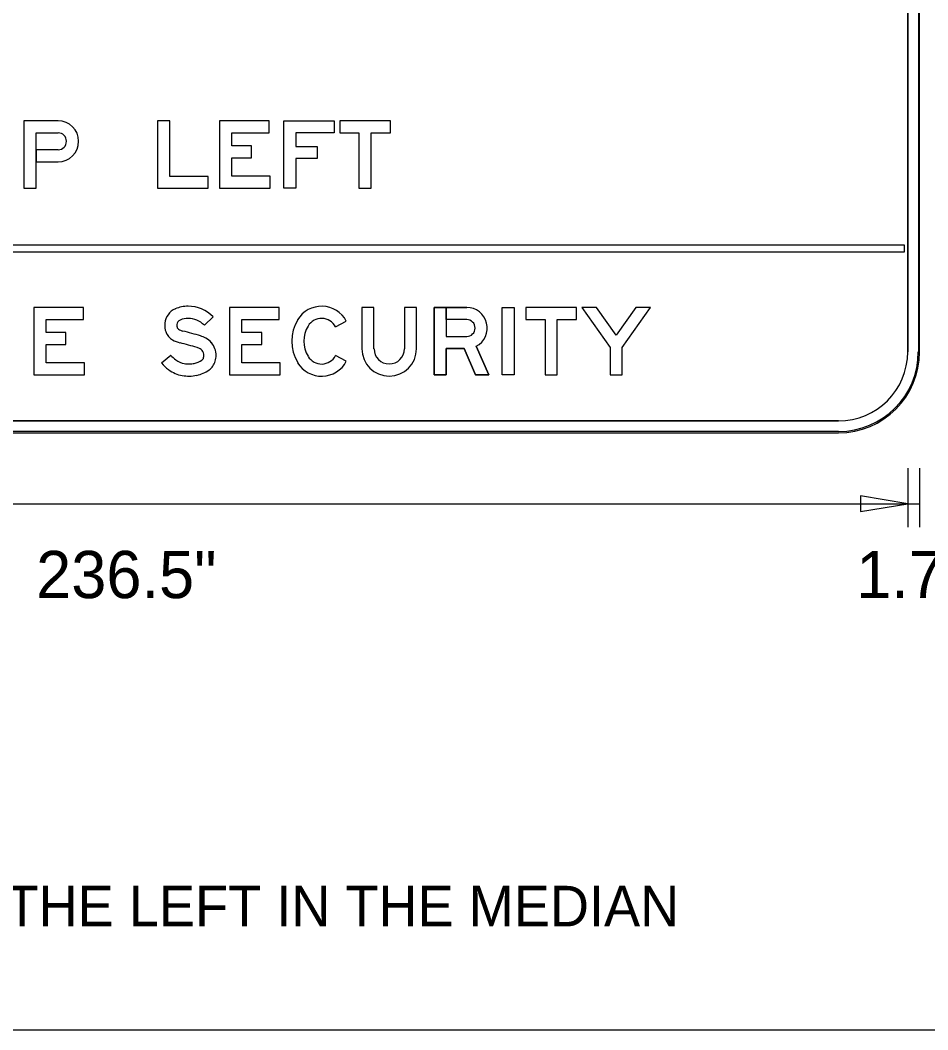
# Model space of a CAD drawing. Extents: x 17890628 to 17890817, y 17897493 to 17897992.
# Drawn here: x 17890707.77 to 17890718.98, y 17897523.4 to 17897535.86 of the extents above; entities that cross this region are included whole.
import ezdxf

# ---------------------------------------------------------------- set-up
doc = ezdxf.new("R2010")
doc.units = 0
for name, color, linetype in [('GSBWFill', 7, 'Continuous'), ('GSColorFill', 7, 'Continuous'), ('GSDims', 7, 'Continuous'), ('GSOutline', 7, 'Continuous'), ('SheetLinesMisc2_dp', 7, 'Continuous')]:
    doc.layers.add(name, color=color, linetype=linetype)

msp = doc.modelspace()

# ---------------------------------------------------------------- linework, layer by layer
at = {"layer": 'GSBWFill'}
for p, q in [((17890718.734, 17897539.769), (17890718.734, 17897531.769)), ((17890718.879, 17897531.769), (17890718.879, 17897539.769)), ((17890707.968, 17897534.471), (17890708.239, 17897534.471)), ((17890718.694, 17897533.087), (17890699.027, 17897533.087)), ((17890718.694, 17897533.004), (17890718.694, 17897533.087)), ((17890699.027, 17897533.004), (17890718.694, 17897533.004)), ((17890712.516, 17897532.316), (17890712.516, 17897531.806)), ((17890711.667, 17897532.077), (17890711.799, 17897532.148)), ((17890711.799, 17897531.652), (17890711.667, 17897531.722)), ((17890711.667, 17897531.722), (17890711.667, 17897531.722)), ((17890717.879, 17897530.915), (17890699.881, 17897530.915)), ((17890699.881, 17897530.769), (17890717.879, 17897530.769))]:
    msp.add_line(p, q, dxfattribs=at)
for points in [[(17890708.239, 17897534.621), (17890707.818, 17897534.621), (17890707.818, 17897533.788), (17890707.968, 17897533.788), (17890707.968, 17897534.471)], [(17890708.239, 17897534.263), (17890707.968, 17897534.263), (17890707.968, 17897534.113), (17890708.239, 17897534.113)], [(17890712.141, 17897531.806), (17890712.141, 17897532.316), (17890711.991, 17897532.316), (17890711.991, 17897531.806)], [(17890712.666, 17897531.806), (17890712.666, 17897532.316), (17890712.516, 17897532.316)], [(17890713.404, 17897531.838), (17890713.558, 17897531.483), (17890713.394, 17897531.483), (17890713.254, 17897531.808), (17890713.033, 17897531.808), (17890713.033, 17897531.483), (17890712.883, 17897531.483), (17890712.883, 17897532.316), (17890713.033, 17897532.316), (17890713.033, 17897531.958), (17890713.286, 17897531.958)], [(17890713.033, 17897532.166), (17890713.033, 17897532.316), (17890713.286, 17897532.316)], [(17890710.153, 17897532.202), (17890710.046, 17897532.097)], [(17890713.286, 17897532.166), (17890713.033, 17897532.166)], [(17890709.516, 17897531.631), (17890709.63, 17897531.729)]]:
    msp.add_lwpolyline(points, dxfattribs=at)
for points in [[(17890710.093, 17897533.788), (17890710.093, 17897533.933), (17890709.618, 17897533.933), (17890709.618, 17897534.621), (17890709.468, 17897534.621), (17890709.468, 17897533.788)], [(17890710.859, 17897533.938), (17890710.384, 17897533.938), (17890710.384, 17897534.162), (17890710.63, 17897534.162), (17890710.63, 17897534.312), (17890710.384, 17897534.312), (17890710.384, 17897534.471), (17890710.847, 17897534.471), (17890710.847, 17897534.621), (17890710.234, 17897534.621), (17890710.234, 17897533.788), (17890710.859, 17897533.788)], [(17890711.176, 17897534.154), (17890711.176, 17897533.788), (17890711.026, 17897533.788), (17890711.026, 17897534.621), (17890711.651, 17897534.621), (17890711.651, 17897534.471), (17890711.176, 17897534.471), (17890711.176, 17897534.304), (17890711.439, 17897534.304), (17890711.439, 17897534.154)], [(17890711.718, 17897534.471), (17890711.955, 17897534.471), (17890711.955, 17897533.788), (17890712.105, 17897533.788), (17890712.105, 17897534.471), (17890712.343, 17897534.471), (17890712.343, 17897534.621), (17890711.718, 17897534.621)], [(17890708.566, 17897531.633), (17890708.091, 17897531.633), (17890708.091, 17897531.857), (17890708.337, 17897531.857), (17890708.337, 17897532.007), (17890708.091, 17897532.007), (17890708.091, 17897532.166), (17890708.554, 17897532.166), (17890708.554, 17897532.316), (17890707.941, 17897532.316), (17890707.941, 17897531.483), (17890708.566, 17897531.483)], [(17890710.983, 17897531.633), (17890710.508, 17897531.633), (17890710.508, 17897531.857), (17890710.754, 17897531.857), (17890710.754, 17897532.007), (17890710.508, 17897532.007), (17890710.508, 17897532.166), (17890710.97, 17897532.166), (17890710.97, 17897532.316), (17890710.358, 17897532.316), (17890710.358, 17897531.483), (17890710.983, 17897531.483)], [(17890713.724, 17897531.483), (17890713.724, 17897532.316), (17890713.874, 17897532.316), (17890713.874, 17897531.483)], [(17890714.016, 17897532.166), (17890714.254, 17897532.166), (17890714.254, 17897531.483), (17890714.404, 17897531.483), (17890714.404, 17897532.166), (17890714.641, 17897532.166), (17890714.641, 17897532.316), (17890714.016, 17897532.316)], [(17890715.208, 17897531.821), (17890715.558, 17897532.316), (17890715.374, 17897532.316), (17890715.133, 17897531.974), (17890714.891, 17897532.316), (17890714.708, 17897532.316), (17890715.058, 17897531.821), (17890715.058, 17897531.483), (17890715.208, 17897531.483)]]:
    msp.add_lwpolyline(points, close=True, dxfattribs=at)
for centre, radius, start, end in [((17890709.774, 17897532.098), 0.218, 113.3248, 174.1421), ((17890709.845, 17897531.933), 0.398, 90, 113.3248), ((17890709.845, 17897531.9), 0.431, 44.4342, 90), ((17890711.494, 17897531.985), 0.346, 28.0265, 148.7499), ((17890713.286, 17897532.062), 0.254, 297.837, 90), ((17890709.774, 17897532.098), 0.0679, 113.3248, 174.1421), ((17890709.845, 17897531.933), 0.248, 90, 113.3248), ((17890709.845, 17897531.9), 0.281, 44.4342, 90), ((17890711.635, 17897531.9), 0.51, 148.7499, 211.2501), ((17890711.494, 17897531.985), 0.196, 28.0265, 148.7499), ((17890713.286, 17897532.062), 0.104, 270, 90), ((17890709.794, 17897532.096), 0.238, 174.1421, 201.2247), ((17890709.794, 17897532.096), 0.0882, 174.1421, 201.2247), ((17890709.745, 17897532.078), 0.0363, 201.2247, 240.1812), ((17890709.831, 17897532.228), 0.209, 240.1812, 256.1067), ((17890708.81, 17897528.098), 4.045, 72.8961, 76.1067), ((17890711.635, 17897531.9), 0.36, 148.7499, 211.2501), ((17890709.745, 17897532.078), 0.186, 201.2247, 240.1812), ((17890709.831, 17897532.228), 0.359, 240.1812, 256.1067), ((17890709.882, 17897531.582), 0.4, 63.0108, 72.8961), ((17890709.963, 17897531.74), 0.222, 39.5561, 63.0108), ((17890708.81, 17897528.098), 3.895, 72.8961, 76.1067), ((17890709.882, 17897531.582), 0.25, 63.0108, 72.8961), ((17890709.963, 17897531.74), 0.0724, 39.5561, 63.0108), ((17890709.942, 17897531.723), 0.0993, 0, 39.5561), ((17890709.942, 17897531.723), 0.249, 0, 39.5561), ((17890712.329, 17897531.806), 0.337, 180, 0), ((17890712.329, 17897531.806), 0.187, 180, 0), ((17890709.955, 17897532.01), 0.43, 220.8202, 232.6492), ((17890709.835, 17897531.852), 0.231, 232.6492, 260.7349), ((17890709.872, 17897531.865), 0.245, 281.6446, 306.0677), ((17890709.983, 17897531.712), 0.0563, 306.0677, 343.4972), ((17890709.948, 17897531.723), 0.0932, 343.4972, 0), ((17890709.983, 17897531.712), 0.206, 306.0677, 343.4972), ((17890709.948, 17897531.723), 0.243, 343.4972, 0), ((17890711.494, 17897531.814), 0.346, 211.2501, 331.9735), ((17890711.494, 17897531.814), 0.196, 211.2501, 331.9735), ((17890717.879, 17897531.769), 1, 270, 0), ((17890717.879, 17897531.769), 0.854, 270, 0), ((17890709.955, 17897532.01), 0.58, 220.8202, 232.6492), ((17890709.835, 17897531.852), 0.381, 232.6492, 260.7349), ((17890709.86, 17897532.007), 0.388, 260.7349, 270), ((17890709.86, 17897531.925), 0.306, 270, 281.6446), ((17890709.872, 17897531.865), 0.395, 281.6446, 306.0677), ((17890709.86, 17897532.007), 0.538, 260.7349, 270), ((17890709.86, 17897531.925), 0.456, 270, 281.6446)]:
    msp.add_arc(centre, radius, start, end, dxfattribs=at)
for major_axis in [(0, 0.254), (0, 0.104)]:
    msp.add_ellipse((17890708.239, 17897534.367), major_axis=major_axis, ratio=0.999997, start_param=3.141593, end_param=6.283185, dxfattribs=at)
at = {"layer": 'GSColorFill'}
for p, q in [((17890718.734, 17897539.769), (17890718.734, 17897531.769)), ((17890718.865, 17897539.769), (17890718.865, 17897531.769)), ((17890718.879, 17897531.769), (17890718.879, 17897539.769)), ((17890718.879, 17897531.769), (17890718.879, 17897539.769)), ((17890718.879, 17897531.769), (17890718.879, 17897539.769)), ((17890707.968, 17897534.471), (17890708.239, 17897534.471)), ((17890718.694, 17897533.087), (17890699.027, 17897533.087)), ((17890718.694, 17897533.004), (17890718.694, 17897533.087)), ((17890699.027, 17897533.004), (17890718.694, 17897533.004)), ((17890712.516, 17897532.316), (17890712.516, 17897531.806)), ((17890711.667, 17897532.077), (17890711.799, 17897532.148)), ((17890711.799, 17897531.652), (17890711.667, 17897531.722)), ((17890711.667, 17897531.722), (17890711.667, 17897531.722)), ((17890717.879, 17897530.915), (17890699.881, 17897530.915)), ((17890717.879, 17897530.784), (17890699.88, 17897530.784)), ((17890699.879, 17897530.769), (17890717.879, 17897530.769)), ((17890699.88, 17897530.769), (17890717.879, 17897530.769)), ((17890699.881, 17897530.769), (17890717.879, 17897530.769))]:
    msp.add_line(p, q, dxfattribs=at)
for points in [[(17890708.239, 17897534.621), (17890707.818, 17897534.621), (17890707.818, 17897533.788), (17890707.968, 17897533.788), (17890707.968, 17897534.471)], [(17890708.239, 17897534.263), (17890707.968, 17897534.263), (17890707.968, 17897534.113), (17890708.239, 17897534.113)], [(17890712.141, 17897531.806), (17890712.141, 17897532.316), (17890711.991, 17897532.316), (17890711.991, 17897531.806)], [(17890712.666, 17897531.806), (17890712.666, 17897532.316), (17890712.516, 17897532.316)], [(17890713.404, 17897531.838), (17890713.558, 17897531.483), (17890713.394, 17897531.483), (17890713.254, 17897531.808), (17890713.033, 17897531.808), (17890713.033, 17897531.483), (17890712.883, 17897531.483), (17890712.883, 17897532.316), (17890713.033, 17897532.316), (17890713.033, 17897531.958), (17890713.286, 17897531.958)], [(17890713.033, 17897532.166), (17890713.033, 17897532.316), (17890713.286, 17897532.316)], [(17890710.153, 17897532.202), (17890710.046, 17897532.097)], [(17890713.286, 17897532.166), (17890713.033, 17897532.166)], [(17890709.516, 17897531.631), (17890709.63, 17897531.729)]]:
    msp.add_lwpolyline(points, dxfattribs=at)
for points in [[(17890710.093, 17897533.788), (17890710.093, 17897533.933), (17890709.618, 17897533.933), (17890709.618, 17897534.621), (17890709.468, 17897534.621), (17890709.468, 17897533.788)], [(17890710.859, 17897533.938), (17890710.384, 17897533.938), (17890710.384, 17897534.162), (17890710.63, 17897534.162), (17890710.63, 17897534.312), (17890710.384, 17897534.312), (17890710.384, 17897534.471), (17890710.847, 17897534.471), (17890710.847, 17897534.621), (17890710.234, 17897534.621), (17890710.234, 17897533.788), (17890710.859, 17897533.788)], [(17890711.176, 17897534.154), (17890711.176, 17897533.788), (17890711.026, 17897533.788), (17890711.026, 17897534.621), (17890711.651, 17897534.621), (17890711.651, 17897534.471), (17890711.176, 17897534.471), (17890711.176, 17897534.304), (17890711.439, 17897534.304), (17890711.439, 17897534.154)], [(17890711.718, 17897534.471), (17890711.955, 17897534.471), (17890711.955, 17897533.788), (17890712.105, 17897533.788), (17890712.105, 17897534.471), (17890712.343, 17897534.471), (17890712.343, 17897534.621), (17890711.718, 17897534.621)], [(17890708.566, 17897531.633), (17890708.091, 17897531.633), (17890708.091, 17897531.857), (17890708.337, 17897531.857), (17890708.337, 17897532.007), (17890708.091, 17897532.007), (17890708.091, 17897532.166), (17890708.554, 17897532.166), (17890708.554, 17897532.316), (17890707.941, 17897532.316), (17890707.941, 17897531.483), (17890708.566, 17897531.483)], [(17890710.983, 17897531.633), (17890710.508, 17897531.633), (17890710.508, 17897531.857), (17890710.754, 17897531.857), (17890710.754, 17897532.007), (17890710.508, 17897532.007), (17890710.508, 17897532.166), (17890710.97, 17897532.166), (17890710.97, 17897532.316), (17890710.358, 17897532.316), (17890710.358, 17897531.483), (17890710.983, 17897531.483)], [(17890713.724, 17897531.483), (17890713.724, 17897532.316), (17890713.874, 17897532.316), (17890713.874, 17897531.483)], [(17890714.016, 17897532.166), (17890714.254, 17897532.166), (17890714.254, 17897531.483), (17890714.404, 17897531.483), (17890714.404, 17897532.166), (17890714.641, 17897532.166), (17890714.641, 17897532.316), (17890714.016, 17897532.316)], [(17890715.208, 17897531.821), (17890715.558, 17897532.316), (17890715.374, 17897532.316), (17890715.133, 17897531.974), (17890714.891, 17897532.316), (17890714.708, 17897532.316), (17890715.058, 17897531.821), (17890715.058, 17897531.483), (17890715.208, 17897531.483)]]:
    msp.add_lwpolyline(points, close=True, dxfattribs=at)
for centre, radius, start, end in [((17890709.774, 17897532.098), 0.218, 113.3248, 174.1421), ((17890709.845, 17897531.933), 0.398, 90, 113.3248), ((17890709.845, 17897531.9), 0.431, 44.4342, 90), ((17890711.494, 17897531.985), 0.346, 28.0265, 148.7499), ((17890713.286, 17897532.062), 0.254, 297.837, 90), ((17890709.774, 17897532.098), 0.0679, 113.3248, 174.1421), ((17890709.845, 17897531.933), 0.248, 90, 113.3248), ((17890709.845, 17897531.9), 0.281, 44.4342, 90), ((17890711.635, 17897531.9), 0.51, 148.7499, 211.2501), ((17890711.494, 17897531.985), 0.196, 28.0265, 148.7499), ((17890713.286, 17897532.062), 0.104, 270, 90), ((17890709.794, 17897532.096), 0.238, 174.1421, 201.2247), ((17890709.794, 17897532.096), 0.0882, 174.1421, 201.2247), ((17890709.745, 17897532.078), 0.0363, 201.2247, 240.1812), ((17890709.831, 17897532.228), 0.209, 240.1812, 256.1067), ((17890708.81, 17897528.098), 4.045, 72.8961, 76.1067), ((17890711.635, 17897531.9), 0.36, 148.7499, 211.2501), ((17890709.745, 17897532.078), 0.186, 201.2247, 240.1812), ((17890709.831, 17897532.228), 0.359, 240.1812, 256.1067), ((17890709.882, 17897531.582), 0.4, 63.0108, 72.8961), ((17890709.963, 17897531.74), 0.222, 39.5561, 63.0108), ((17890708.81, 17897528.098), 3.895, 72.8961, 76.1067), ((17890709.882, 17897531.582), 0.25, 63.0108, 72.8961), ((17890709.963, 17897531.74), 0.0724, 39.5561, 63.0108), ((17890709.942, 17897531.723), 0.0993, 0, 39.5561), ((17890709.942, 17897531.723), 0.249, 0, 39.5561), ((17890712.329, 17897531.806), 0.337, 180, 0), ((17890712.329, 17897531.806), 0.187, 180, 0), ((17890709.955, 17897532.01), 0.43, 220.8202, 232.6492), ((17890709.835, 17897531.852), 0.231, 232.6492, 260.7349), ((17890709.872, 17897531.865), 0.245, 281.6446, 306.0677), ((17890709.983, 17897531.712), 0.0563, 306.0677, 343.4972), ((17890709.948, 17897531.723), 0.0932, 343.4972, 0), ((17890709.983, 17897531.712), 0.206, 306.0677, 343.4972), ((17890709.948, 17897531.723), 0.243, 343.4972, 0), ((17890711.494, 17897531.814), 0.346, 211.2501, 331.9735), ((17890711.494, 17897531.814), 0.196, 211.2501, 331.9735), ((17890717.879, 17897531.769), 1, 270, 0), ((17890717.879, 17897531.769), 1, 270, 0), ((17890717.879, 17897531.769), 0.854, 270, 0), ((17890717.879, 17897531.769), 1, 270, 0), ((17890717.879, 17897531.769), 0.985, 270, 0), ((17890709.955, 17897532.01), 0.58, 220.8202, 232.6492), ((17890709.835, 17897531.852), 0.381, 232.6492, 260.7349), ((17890709.86, 17897532.007), 0.388, 260.7349, 270), ((17890709.86, 17897531.925), 0.306, 270, 281.6446), ((17890709.872, 17897531.865), 0.395, 281.6446, 306.0677), ((17890709.86, 17897532.007), 0.538, 260.7349, 270), ((17890709.86, 17897531.925), 0.456, 270, 281.6446)]:
    msp.add_arc(centre, radius, start, end, dxfattribs=at)
for major_axis in [(0, 0.254), (0, 0.104)]:
    msp.add_ellipse((17890708.239, 17897534.367), major_axis=major_axis, ratio=0.999997, start_param=3.141593, end_param=6.283185, dxfattribs=at)
at = {"layer": 'GSDims'}
for p, q in [((17890718.734, 17897530.332), (17890718.734, 17897529.603)), ((17890718.88, 17897530.332), (17890718.88, 17897529.603)), ((17890699.025, 17897529.894), (17890718.713, 17897529.894)), ((17890718.713, 17897529.894), (17890718.734, 17897529.894)), ((17890718.734, 17897529.894), (17890718.88, 17897529.894))]:
    msp.add_line(p, q, dxfattribs=at)
msp.add_lwpolyline([(17890718.734, 17897529.894), (17890718.15, 17897529.992), (17890718.15, 17897529.797)], close=True, dxfattribs=at)
at = {"layer": 'GSOutline'}
for p, q in [((17890718.734, 17897531.769), (17890718.734, 17897539.769)), ((17890718.879, 17897531.769), (17890718.879, 17897539.769)), ((17890707.968, 17897534.471), (17890708.239, 17897534.471)), ((17890707.968, 17897534.113), (17890708.239, 17897534.113)), ((17890718.694, 17897533.087), (17890699.027, 17897533.087)), ((17890718.694, 17897533.004), (17890718.694, 17897533.087)), ((17890699.027, 17897533.004), (17890718.694, 17897533.004)), ((17890712.516, 17897532.316), (17890712.516, 17897531.806)), ((17890711.667, 17897532.077), (17890711.799, 17897532.148)), ((17890711.799, 17897531.652), (17890711.667, 17897531.722)), ((17890711.667, 17897531.722), (17890711.667, 17897531.722)), ((17890699.879, 17897530.915), (17890717.879, 17897530.915)), ((17890699.879, 17897530.769), (17890717.879, 17897530.769))]:
    msp.add_line(p, q, dxfattribs=at)
for points in [[(17890708.239, 17897534.621), (17890707.818, 17897534.621), (17890707.818, 17897533.788), (17890707.968, 17897533.788), (17890707.968, 17897534.113)], [(17890708.239, 17897534.263), (17890707.968, 17897534.263), (17890707.968, 17897534.471)], [(17890712.141, 17897531.806), (17890712.141, 17897532.316), (17890711.991, 17897532.316), (17890711.991, 17897531.806)], [(17890712.666, 17897531.806), (17890712.666, 17897532.316), (17890712.516, 17897532.316)], [(17890713.286, 17897532.316), (17890712.883, 17897532.316), (17890712.883, 17897531.483), (17890713.033, 17897531.483), (17890713.033, 17897531.808), (17890713.254, 17897531.808), (17890713.394, 17897531.483), (17890713.558, 17897531.483), (17890713.404, 17897531.838)], [(17890710.153, 17897532.202), (17890710.046, 17897532.097)], [(17890713.286, 17897532.166), (17890713.033, 17897532.166), (17890713.033, 17897531.958), (17890713.286, 17897531.958)], [(17890709.516, 17897531.631), (17890709.63, 17897531.729)]]:
    msp.add_lwpolyline(points, dxfattribs=at)
for points in [[(17890710.093, 17897533.788), (17890710.093, 17897533.933), (17890709.618, 17897533.933), (17890709.618, 17897534.621), (17890709.468, 17897534.621), (17890709.468, 17897533.788)], [(17890710.859, 17897533.938), (17890710.384, 17897533.938), (17890710.384, 17897534.162), (17890710.63, 17897534.162), (17890710.63, 17897534.312), (17890710.384, 17897534.312), (17890710.384, 17897534.471), (17890710.847, 17897534.471), (17890710.847, 17897534.621), (17890710.234, 17897534.621), (17890710.234, 17897533.788), (17890710.859, 17897533.788)], [(17890711.176, 17897534.154), (17890711.176, 17897533.788), (17890711.026, 17897533.788), (17890711.026, 17897534.621), (17890711.651, 17897534.621), (17890711.651, 17897534.471), (17890711.176, 17897534.471), (17890711.176, 17897534.304), (17890711.439, 17897534.304), (17890711.439, 17897534.154)], [(17890711.718, 17897534.471), (17890711.955, 17897534.471), (17890711.955, 17897533.788), (17890712.105, 17897533.788), (17890712.105, 17897534.471), (17890712.343, 17897534.471), (17890712.343, 17897534.621), (17890711.718, 17897534.621)], [(17890708.566, 17897531.633), (17890708.091, 17897531.633), (17890708.091, 17897531.857), (17890708.337, 17897531.857), (17890708.337, 17897532.007), (17890708.091, 17897532.007), (17890708.091, 17897532.166), (17890708.554, 17897532.166), (17890708.554, 17897532.316), (17890707.941, 17897532.316), (17890707.941, 17897531.483), (17890708.566, 17897531.483)], [(17890710.983, 17897531.633), (17890710.508, 17897531.633), (17890710.508, 17897531.857), (17890710.754, 17897531.857), (17890710.754, 17897532.007), (17890710.508, 17897532.007), (17890710.508, 17897532.166), (17890710.97, 17897532.166), (17890710.97, 17897532.316), (17890710.358, 17897532.316), (17890710.358, 17897531.483), (17890710.983, 17897531.483)], [(17890713.724, 17897531.483), (17890713.724, 17897532.316), (17890713.874, 17897532.316), (17890713.874, 17897531.483)], [(17890714.016, 17897532.166), (17890714.254, 17897532.166), (17890714.254, 17897531.483), (17890714.404, 17897531.483), (17890714.404, 17897532.166), (17890714.641, 17897532.166), (17890714.641, 17897532.316), (17890714.016, 17897532.316)], [(17890715.208, 17897531.821), (17890715.558, 17897532.316), (17890715.374, 17897532.316), (17890715.133, 17897531.974), (17890714.891, 17897532.316), (17890714.708, 17897532.316), (17890715.058, 17897531.821), (17890715.058, 17897531.483), (17890715.208, 17897531.483)]]:
    msp.add_lwpolyline(points, close=True, dxfattribs=at)
for centre, radius, start, end in [((17890709.774, 17897532.098), 0.218, 113.3248, 174.1421), ((17890709.845, 17897531.933), 0.398, 90, 113.3248), ((17890709.845, 17897531.9), 0.431, 44.4342, 90), ((17890711.494, 17897531.985), 0.346, 28.0265, 148.7499), ((17890713.286, 17897532.062), 0.254, 297.837, 90), ((17890709.774, 17897532.098), 0.0679, 113.3248, 174.1421), ((17890709.845, 17897531.933), 0.248, 90, 113.3248), ((17890709.845, 17897531.9), 0.281, 44.4342, 90), ((17890711.635, 17897531.9), 0.51, 148.7499, 211.2501), ((17890711.494, 17897531.985), 0.196, 28.0265, 148.7499), ((17890713.286, 17897532.062), 0.104, 270, 90), ((17890709.794, 17897532.096), 0.238, 174.1421, 201.2247), ((17890709.794, 17897532.096), 0.0882, 174.1421, 201.2247), ((17890709.745, 17897532.078), 0.0363, 201.2247, 240.1812), ((17890709.831, 17897532.228), 0.209, 240.1812, 256.1067), ((17890708.81, 17897528.098), 4.045, 72.8961, 76.1067), ((17890711.635, 17897531.9), 0.36, 148.7499, 211.2501), ((17890709.745, 17897532.078), 0.186, 201.2247, 240.1812), ((17890709.831, 17897532.228), 0.359, 240.1812, 256.1067), ((17890709.882, 17897531.582), 0.4, 63.0108, 72.8961), ((17890709.963, 17897531.74), 0.222, 39.5561, 63.0108), ((17890708.81, 17897528.098), 3.895, 72.8961, 76.1067), ((17890709.882, 17897531.582), 0.25, 63.0108, 72.8961), ((17890709.963, 17897531.74), 0.0724, 39.5561, 63.0108), ((17890709.942, 17897531.723), 0.0993, 0, 39.5561), ((17890709.942, 17897531.723), 0.249, 0, 39.5561), ((17890712.329, 17897531.806), 0.337, 180, 0), ((17890712.329, 17897531.806), 0.187, 180, 0), ((17890709.955, 17897532.01), 0.43, 220.8202, 232.6492), ((17890709.835, 17897531.852), 0.231, 232.6492, 260.7349), ((17890709.872, 17897531.865), 0.245, 281.6446, 306.0677), ((17890709.983, 17897531.712), 0.0563, 306.0677, 343.4972), ((17890709.948, 17897531.723), 0.0932, 343.4972, 0), ((17890709.983, 17897531.712), 0.206, 306.0677, 343.4972), ((17890709.948, 17897531.723), 0.243, 343.4972, 0), ((17890711.494, 17897531.814), 0.346, 211.2501, 331.9735), ((17890711.494, 17897531.814), 0.196, 211.2501, 331.9735), ((17890717.879, 17897531.769), 1, 270, 0), ((17890717.879, 17897531.769), 0.854, 270, 0), ((17890709.955, 17897532.01), 0.58, 220.8202, 232.6492), ((17890709.835, 17897531.852), 0.381, 232.6492, 260.7349), ((17890709.86, 17897532.007), 0.388, 260.7349, 270), ((17890709.86, 17897531.925), 0.306, 270, 281.6446), ((17890709.872, 17897531.865), 0.395, 281.6446, 306.0677), ((17890709.86, 17897532.007), 0.538, 260.7349, 270), ((17890709.86, 17897531.925), 0.456, 270, 281.6446)]:
    msp.add_arc(centre, radius, start, end, dxfattribs=at)
for major_axis in [(0, 0.254), (0, 0.104)]:
    msp.add_ellipse((17890708.239, 17897534.367), major_axis=major_axis, ratio=0.999997, start_param=3.141593, end_param=6.283185, dxfattribs=at)
at = {"layer": 'SheetLinesMisc2_dp'}
msp.add_line((17890684.628, 17897523.399), (17890735.8, 17897523.399), dxfattribs=at)

# ---------------------------------------------------------------- texts
at = {"layer": 'GSDims'}
for s, height, p in [('236.5"', 0.5833, (17890707.968, 17897528.728)), ('1.75"', 0.5833, (17890718.097, 17897528.728)), ('TYPICAL: FINAL SIGN BEFORE ENTRY TO THE PLAZA. INSTALLED ON THE LEFT IN THE MEDIAN', 0.5, (17890685.001, 17897524.677))]:
    msp.add_text(s, height=height, dxfattribs=at).set_placement(p)

doc.saveas('drawing.dxf')
